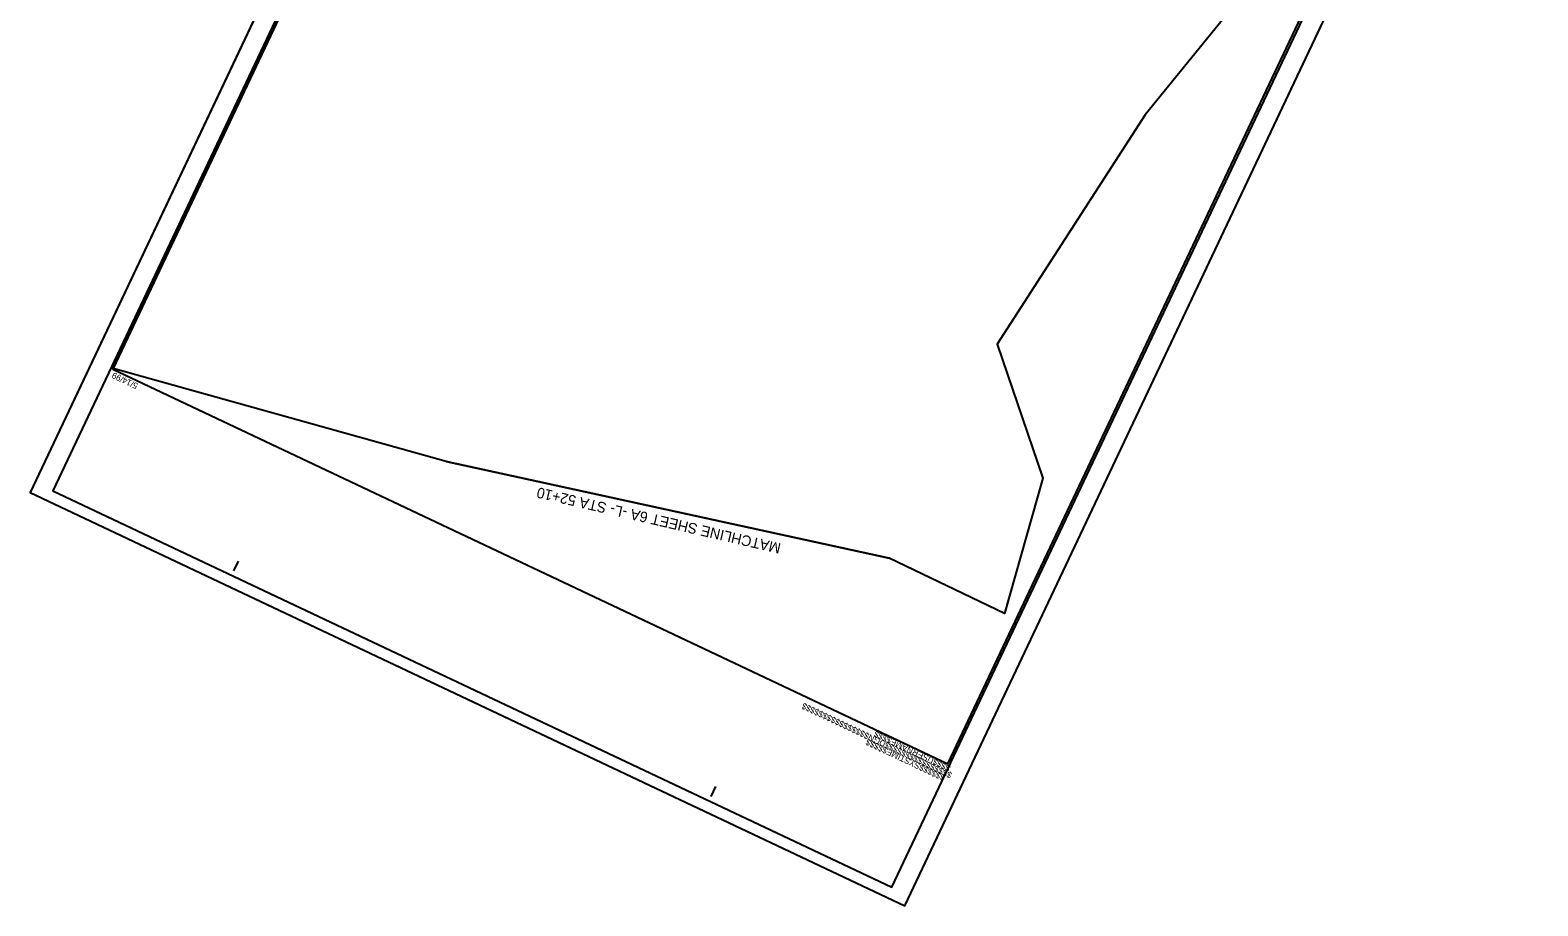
# Model space of a CAD drawing. Extents: x 556536 to 558250, y 505355 to 507347.
# Drawn here: x 556536 to 558250, y 505355 to 506351 of the extents above; entities that cross this region are included whole.
import ezdxf

# ---------------------------------------------------------------- set-up
doc = ezdxf.new("R2010")
doc.units = 0
for name, color, linetype in [('Matchline', 7, 'Continuous'), ('Matchline Text', 7, 'Continuous'), ('Prop Horizontal Alignment Direction Label', 7, 'Continuous'), ('Prop SS Cut Line', 7, 'Continuous'), ('Prop SS Fill Line', 7, 'Continuous'), ('Scratch_Level_9', 7, 'Continuous'), ('Sheet Clip Boundary CELL', 7, 'Continuous')]:
    doc.layers.add(name, color=color, linetype=linetype)

msp = doc.modelspace()

# ---------------------------------------------------------------- linework, layer by layer
at = {"layer": 'Matchline'}
msp.add_line((557008.7, 505860.1), (557512.4, 505750.3), dxfattribs=at)
at = {"layer": 'Prop Horizontal Alignment Direction Label'}
msp.add_lwpolyline([(557255.4, 507347.2), (556535.8, 505824.7), (557530.3, 505354.6), (558249.9, 506877.1)], close=True, dxfattribs=at)
at = {"layer": 'Prop SS Cut Line'}
for p, q in [((556630.1, 505965.9), (556630.1, 505965.9)), ((556767.4, 505735.6), (556772.8, 505746.9)), ((557309.9, 505479.2), (557315.2, 505490.5))]:
    msp.add_line(p, q, dxfattribs=at)
msp.add_lwpolyline([(557270.7, 507321.1), (556629.7, 505965), (557579, 505516.3), (558220, 506872.4)], close=True, dxfattribs=at)
at = {"layer": 'Prop SS Fill Line'}
msp.add_lwpolyline([(557273.7, 507333.5), (556561.6, 505826.8), (557515.5, 505375.9), (558227.7, 506882.6)], close=True, dxfattribs=at)
at = {"layer": 'Scratch_Level_9'}
for p, q in [((557255.4, 507347.2), (556535.8, 505824.7)), ((557530.3, 505354.6), (558249.9, 506877.1)), ((556535.8, 505824.7), (557530.3, 505354.6))]:
    msp.add_line(p, q, dxfattribs=at)
at = {"layer": 'Sheet Clip Boundary CELL'}
msp.add_lwpolyline([(557803.3, 506254.6), (557635.3, 505993.6), (557687.2, 505841), (557643.4, 505687.1), (557512.4, 505750.3), (557008.7, 505860.1), (556630.1, 505965.9), (557185.2, 507140.2), (557323.6, 507073.6), (557367.3, 507166.4), (557435.1, 507139.3), (557448.3, 507074.9), (557454, 507069.8), (557474, 506970.7), (557395.1, 506959.8), (557425.5, 506933.6), (557889.7, 506539.4), (557951.7, 506501.5), (557971.1, 506460.7)], close=True, dxfattribs=at)

# ---------------------------------------------------------------- texts
at = {"layer": 'Matchline Text'}
msp.add_text('MATCHLINE SHEET 6A -L- STA 52+10', height=12, rotation=166.9353, dxfattribs=at).set_placement((557390.1, 505766.8))
at = {"layer": 'Prop SS Cut Line'}
for s, p in [('5/14/99', (556659, 505948.6)), ('$$$$$$$$$$$$$$$$DGN$$$$$$$$$$$$$$$$', (557584.6, 505505.7)), ('$$$$USERNAME$$$$', (557582.9, 505513.5)), ('$$$$$$SYSTIME$$$$$', (557576.8, 505502.7))]:
    msp.add_text(s, height=7, rotation=154.7021, dxfattribs=at).set_placement(p)

doc.saveas('drawing.dxf')
